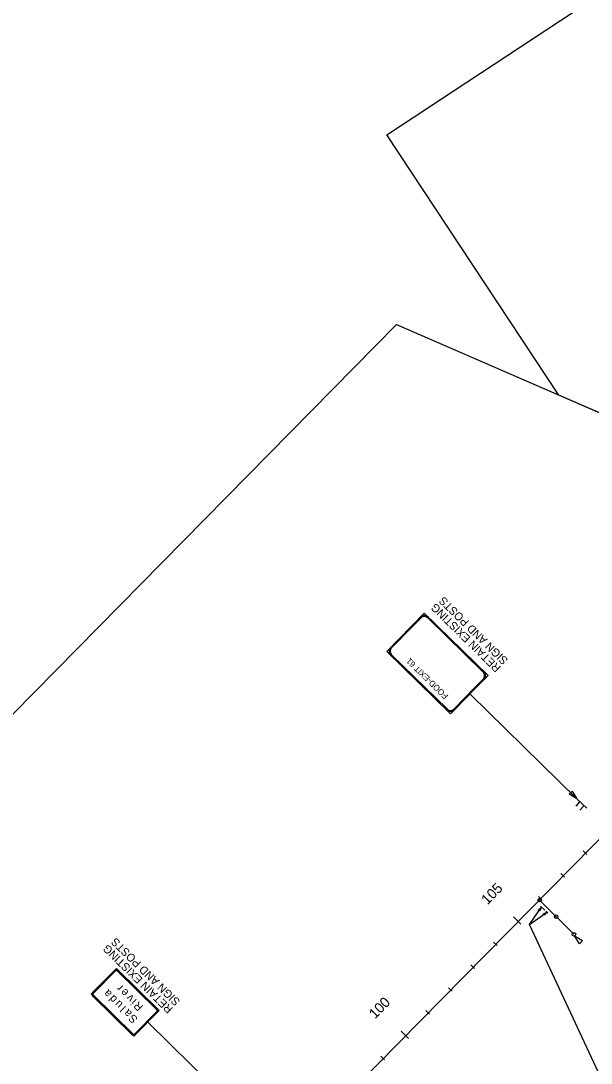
# Model space of a CAD drawing. Extents: x -5665 to 1997148, y 4 to 827579.
# Drawn here: x 1960479 to 1962258, y 798163 to 801417 of the extents above; entities that cross this region are included whole.
import ezdxf

# ---------------------------------------------------------------- set-up
doc = ezdxf.new("R2010")
doc.units = 0
for name, color, linetype in [('RD_HC_CL_Rel', 7, 'Continuous'), ('RD_HC_Data_Tic_Rel', 7, 'Continuous'), ('RD_HC_TX_Rel_Sta50', 7, 'Continuous'), ('RD_PD_Final_TX', 7, 'Continuous'), ('RD_SHT_ShtClip', 7, 'Continuous'), ('TR SN EXTRUDED PANEL SIGNS- MOUNTED OVERHEAD', 7, 'Continuous')]:
    doc.layers.add(name, color=color, linetype=linetype)

msp = doc.modelspace()

# ---------------------------------------------------------------- linework, layer by layer
at = {"layer": 'RD_HC_CL_Rel'}
msp.add_line((1957622, 794124.4), (1963740.1, 800343.8), dxfattribs=at)
at = {"layer": 'RD_HC_Data_Tic_Rel'}
for p, q in [((1962244.6, 798814.9), (1962233.2, 798826.2)), ((1962174.4, 798743.6), (1962163, 798754.9)), ((1962104.3, 798672.4), (1962092.9, 798683.6)), ((1962038.5, 798596.9), (1962015.6, 798619.3)), ((1961964, 798529.8), (1961952.6, 798541)), ((1961893.9, 798458.5), (1961882.5, 798469.7)), ((1961823.8, 798387.2), (1961812.4, 798398.4)), ((1961753.7, 798315.9), (1961742.3, 798327.1)), ((1961687.8, 798240.4), (1961665, 798262.9)), ((1961613.4, 798173.3), (1961602, 798184.6))]:
    msp.add_line(p, q, dxfattribs=at)
at = {"layer": 'RD_PD_Final_TX'}
for points in [[(1962188.8, 799002.4), (1962198.4, 799012.2), (1962213.3, 798988)], [(1962230.6, 798545.8), (1962221, 798536), (1962206.1, 798560.2)]]:
    msp.add_lwpolyline(points, close=True, dxfattribs=at)
at = {"layer": 'RD_SHT_ShtClip'}
for points in [[(1962404, 800141.4), (1962156.8, 800249.1), (1961619.9, 801061.9), (1967047, 804639.1), (1967746.1, 803578.5), (1967695.1, 802969), (1968000.2, 801689.9), (1968522.9, 801587.9), (1968575.1, 801281.2), (1968568.4, 800839.6), (1968542.7, 800594.7), (1964601.3, 797996.7), (1963740.9, 798826.2)], [(1962404, 800141.4), (1963753.3, 798814), (1964835.2, 797771.3), (1960364.2, 793199.8), (1958829.3, 794809.7), (1958381.6, 795250.1), (1957464.7, 796215.1), (1961650.1, 800469.8)]]:
    msp.add_lwpolyline(points, close=True, dxfattribs=at)
at = {"layer": 'TR SN EXTRUDED PANEL SIGNS- MOUNTED OVERHEAD'}
for p, q in [((1962213.3, 798988), (1961880.4, 799315.4)), ((1962210.4, 798965.8), (1962222.7, 798978.8)), ((1962243.9, 798958.8), (1962214, 798986.9)), ((1962222.8, 798953.3), (1962235, 798966.3)), ((1962096.6, 798671.7), (1962203.7, 798565.4)), ((1962099.7, 798653.4), (1962112.8, 798640.4)), ((1962064.8, 798595.8), (1962101.8, 798649.1)), ((1962064.8, 798595.8), (1962118.5, 798633.3)), ((1962116.3, 798637.6), (1962122.1, 798631.8)), ((1962326.5, 798035.3), (1962064.8, 798595.8)), ((1961220, 797951.2), (1960874.7, 798291))]:
    msp.add_line(p, q, dxfattribs=at)
for points in [[(1961936.1, 799373.2), (1961736.7, 799568.2), (1961697.8, 799528.3)], [(1961726, 799552.7), (1961700, 799526.1)], [(1961920.6, 799384), (1961747.9, 799553)], [(1961697.8, 799528.3), (1961619.8, 799448.6), (1961819.1, 799253.6), (1961897.1, 799333.4), (1961897.1, 799333.4)], [(1961700, 799526.1), (1961635, 799459.7)], [(1961635.2, 799437.8), (1961808, 799268.8)], [(1961897.1, 799333.4), (1961936.1, 799373.2), (1961936.1, 799373.2)], [(1961894.9, 799335.5), (1961920.9, 799362.1)], [(1961829.9, 799269.1), (1961894.9, 799335.5)], [(1961897.1, 799333.4), (1961832.1, 799266.9)], [(1960910.2, 798327.1), (1960776.5, 798458.6), (1960697.6, 798378.4), (1960831.3, 798246.9), (1960910.2, 798327.1), (1960910.2, 798327.1), (1960910.2, 798327.1)], [(1960702.5, 798383.4), (1960771.6, 798453.6)], [(1960773.8, 798451.4), (1960704.8, 798381.2)], [(1960773.8, 798451.4), (1960773.8, 798451.4), (1960773.8, 798451.4)], [(1960903, 798329.8), (1960779.3, 798451.4)], [(1960781.5, 798453.6), (1960905.1, 798332)], [(1960826.3, 798251.8), (1960702.6, 798373.4)], [(1960704.8, 798375.7), (1960828.4, 798254)], [(1960704.8, 798375.7), (1960704.8, 798375.7), (1960704.8, 798375.7)], [(1960903, 798329.8), (1960903, 798329.8), (1960903, 798329.8)], [(1960834, 798254.1), (1960903, 798324.3)], [(1960905.2, 798322.1), (1960836.2, 798251.9)], [(1960834, 798254.1), (1960834, 798254.1), (1960834, 798254.1)]]:
    msp.add_lwpolyline(points, dxfattribs=at)
for points in [[(1962097.8, 798638.5), (1962093.3, 798641.7), (1962101.8, 798649.1)], [(1962111.1, 798624.8), (1962107.9, 798629.3), (1962118.5, 798633.3)]]:
    msp.add_lwpolyline(points, close=True, dxfattribs=at)
for centre in [(1962096.8, 798671.8), (1962148.5, 798620.2), (1962203.8, 798565.3)]:
    msp.add_circle(centre, 5.54, dxfattribs=at)
for centre, radius, start, end in [((1961737, 799541.9), 18.6, 45.6377, 135.6379), ((1961737, 799541.9), 15.5, 45.6377, 135.6379), ((1961646.1, 799448.9), 18.6, 135.6376, 225.6379), ((1961646.1, 799448.9), 15.5, 135.6376, 225.6379), ((1961909.8, 799372.9), 15.5, 315.6375, 45.6377), ((1961909.8, 799372.9), 18.6, 315.6375, 45.6377), ((1961818.8, 799279.9), 18.6, 225.6379, 315.6375), ((1961818.8, 799279.9), 15.5, 225.6379, 315.6375), ((1960776.6, 798448.6), 7.03, 45.4705, 135.4707), ((1960776.6, 798448.6), 3.91, 45.4705, 135.4707), ((1960707.5, 798378.4), 7.03, 135.4705, 225.4707), ((1960707.5, 798378.4), 3.91, 135.4705, 225.4707), ((1960900.2, 798327), 3.91, 315.4703, 45.4705), ((1960900.2, 798327), 7.03, 315.4703, 45.4705), ((1960831.2, 798256.8), 7.03, 225.4707, 315.4703), ((1960831.2, 798256.8), 3.91, 225.4707, 315.4703)]:
    msp.add_arc(centre, radius, start, end, dxfattribs=at)

# ---------------------------------------------------------------- texts
at = {"layer": 'RD_HC_TX_Rel_Sta50'}
for s, p in [('105', (1961934.2, 798655.7)), ('100', (1961583.5, 798299.2))]:
    msp.add_text(s, height=32, rotation=45.4705, dxfattribs=at).set_placement(p)
at = {"layer": 'TR SN EXTRUDED PANEL SIGNS- MOUNTED OVERHEAD'}
for s, height, rotation, p in [('SIGN AND POSTS', 25, 135.4569, (1962000.4, 799422.2)), ('RETAIN EXISTING', 25, 135.4569, (1961977.5, 799399)), ('FOOD-EXIT 61', 18.587, 135.6376, (1961813.5, 799310.9)), ('RETAIN EXISTING', 25, 135.4705, (1960954.7, 798333.9)), ('SIGN AND POSTS', 25, 135.4705, (1960977.5, 798357.1)), ('a', 25, 135.4705, (1960764.2, 798381.9)), ('r', 25, 135.4705, (1960799.4, 798402.1)), ('e', 25, 135.4705, (1960816.6, 798385.2)), ('d', 25, 135.4705, (1960781.2, 798365.1)), ('v', 25, 135.4705, (1960833.5, 798368.5)), ('i', 25, 135.4705, (1960841.9, 798360.2)), ('u', 25, 135.4705, (1960798.3, 798348.3)), ('l', 25, 135.4705, (1960808.5, 798338.3)), ('a', 25, 135.4705, (1960826.8, 798320.3)), ('R', 25, 135.4705, (1960862.1, 798340.4)), ('S', 25, 135.4705, (1960845.2, 798302.2))]:
    msp.add_text(s, height=height, rotation=rotation, dxfattribs=at).set_placement(p)

doc.saveas('drawing.dxf')
